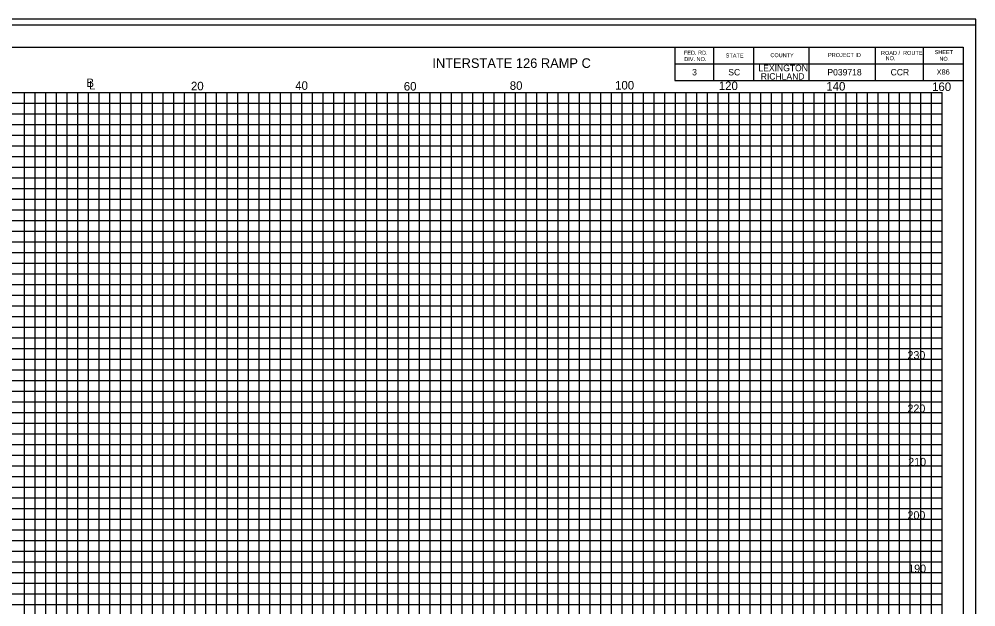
# Model space of a CAD drawing. Extents: x 967 to 1326, y 964 to 2584.
# Drawn here: x 1147 to 1326.3, y 1353.6 to 1463.7 of the extents above; entities that cross this region are included whole.
import ezdxf

# ---------------------------------------------------------------- set-up
doc = ezdxf.new("R2010")
doc.units = 0
for name, color, linetype in [('Default', 7, 'Continuous'), ('RD_SHT_Bndy', 7, 'Continuous'), ('RD_SHT_IplotShp', 7, 'Continuous'), ('RD_SHT_MjGrid', 7, 'Continuous'), ('RD_SHT_MnGrid', 7, 'Continuous'), ('RD_SHT_TX', 7, 'Continuous'), ('RD_Sketch1', 7, 'Continuous')]:
    doc.layers.add(name, color=color, linetype=linetype)

msp = doc.modelspace()

# ---------------------------------------------------------------- linework, layer by layer
at = {"layer": 'RD_SHT_Bndy'}
for p, q in [((996.11, 1458.46), (1323.89, 1458.46)), ((1269.89, 1458.46), (1269.89, 1452.21)), ((1277.14, 1458.46), (1277.14, 1452.21)), ((1284.64, 1458.46), (1284.64, 1452.21)), ((1295, 1458.46), (1295, 1452.21)), ((1307.43, 1458.46), (1307.43, 1452.21)), ((1316.39, 1458.46), (1316.39, 1452.21)), ((1323.89, 1458.46), (1323.89, 1248.98)), ((1269.89, 1455.33), (1323.89, 1455.33)), ((1269.89, 1452.21), (1323.89, 1452.21))]:
    msp.add_line(p, q, dxfattribs=at)
at = {"layer": 'RD_SHT_IplotShp'}
for points in [[(967.41, 1243.72), (1326.28, 1243.72), (1326.28, 1463.72), (967.41, 1463.72)], [(988.52, 1244.84), (1326.28, 1244.84), (1326.28, 1462.6), (988.52, 1462.6)]]:
    msp.add_lwpolyline(points, close=True, dxfattribs=at)
at = {"layer": 'RD_SHT_MjGrid'}
for p, q in [((1000, 1450), (1320, 1450)), ((1150, 1280), (1150, 1450)), ((1160, 1280), (1160, 1450)), ((1170, 1280), (1170, 1450)), ((1180, 1280), (1180, 1450)), ((1190, 1280), (1190, 1450)), ((1200, 1280), (1200, 1450)), ((1210, 1280), (1210, 1450)), ((1220, 1280), (1220, 1450)), ((1230, 1280), (1230, 1450)), ((1240, 1280), (1240, 1450)), ((1250, 1280), (1250, 1450)), ((1260, 1280), (1260, 1450)), ((1270, 1280), (1270, 1450)), ((1280, 1280), (1280, 1450)), ((1290, 1280), (1290, 1450)), ((1300, 1280), (1300, 1450)), ((1310, 1280), (1310, 1450)), ((1320, 1280), (1320, 1450)), ((1000, 1440), (1320, 1440)), ((1000, 1430), (1320, 1430)), ((1000, 1420), (1320, 1420)), ((1000, 1410), (1320, 1410)), ((1000, 1400), (1320, 1400)), ((1000, 1390), (1320, 1390)), ((1000, 1380), (1320, 1380)), ((1000, 1370), (1320, 1370)), ((1000, 1360), (1320, 1360))]:
    msp.add_line(p, q, dxfattribs=at)
at = {"layer": 'RD_SHT_MnGrid'}
for p, q in [((1148, 1280), (1148, 1450)), ((1152, 1280), (1152, 1450)), ((1154, 1280), (1154, 1450)), ((1156, 1280), (1156, 1450)), ((1158, 1280), (1158, 1450)), ((1162, 1280), (1162, 1450)), ((1164, 1280), (1164, 1450)), ((1166, 1280), (1166, 1450)), ((1168, 1280), (1168, 1450)), ((1172, 1280), (1172, 1450)), ((1174, 1280), (1174, 1450)), ((1176, 1280), (1176, 1450)), ((1178, 1280), (1178, 1450)), ((1182, 1280), (1182, 1450)), ((1184, 1280), (1184, 1450)), ((1186, 1280), (1186, 1450)), ((1188, 1280), (1188, 1450)), ((1192, 1280), (1192, 1450)), ((1194, 1280), (1194, 1450)), ((1196, 1280), (1196, 1450)), ((1198, 1280), (1198, 1450)), ((1202, 1280), (1202, 1450)), ((1204, 1280), (1204, 1450)), ((1206, 1280), (1206, 1450)), ((1208, 1280), (1208, 1450)), ((1212, 1280), (1212, 1450)), ((1214, 1280), (1214, 1450)), ((1216, 1280), (1216, 1450)), ((1218, 1280), (1218, 1450)), ((1222, 1280), (1222, 1450)), ((1224, 1280), (1224, 1450)), ((1226, 1280), (1226, 1450)), ((1228, 1280), (1228, 1450)), ((1232, 1280), (1232, 1450)), ((1234, 1280), (1234, 1450)), ((1236, 1280), (1236, 1450)), ((1238, 1280), (1238, 1450)), ((1242, 1280), (1242, 1450)), ((1244, 1280), (1244, 1450)), ((1246, 1280), (1246, 1450)), ((1248, 1280), (1248, 1450)), ((1252, 1280), (1252, 1450)), ((1254, 1280), (1254, 1450)), ((1256, 1280), (1256, 1450)), ((1258, 1280), (1258, 1450)), ((1262, 1280), (1262, 1450)), ((1264, 1280), (1264, 1450)), ((1266, 1280), (1266, 1450)), ((1268, 1280), (1268, 1450)), ((1272, 1280), (1272, 1450)), ((1274, 1280), (1274, 1450)), ((1276, 1280), (1276, 1450)), ((1278, 1280), (1278, 1450)), ((1282, 1280), (1282, 1450)), ((1284, 1280), (1284, 1450)), ((1286, 1280), (1286, 1450)), ((1288, 1280), (1288, 1450)), ((1292, 1280), (1292, 1450)), ((1294, 1280), (1294, 1450)), ((1296, 1280), (1296, 1450)), ((1298, 1280), (1298, 1450)), ((1302, 1280), (1302, 1450)), ((1304, 1280), (1304, 1450)), ((1306, 1280), (1306, 1450)), ((1308, 1280), (1308, 1450)), ((1312, 1280), (1312, 1450)), ((1314, 1280), (1314, 1450)), ((1316, 1280), (1316, 1450)), ((1318, 1280), (1318, 1450)), ((1000, 1448), (1320, 1448)), ((1000, 1446), (1320, 1446)), ((1000, 1444), (1320, 1444)), ((1000, 1442), (1320, 1442)), ((1000, 1438), (1320, 1438)), ((1000, 1436), (1320, 1436)), ((1000, 1434), (1320, 1434)), ((1000, 1432), (1320, 1432)), ((1000, 1428), (1320, 1428)), ((1000, 1426), (1320, 1426)), ((1000, 1424), (1320, 1424)), ((1000, 1422), (1320, 1422)), ((1000, 1418), (1320, 1418)), ((1000, 1416), (1320, 1416)), ((1000, 1414), (1320, 1414)), ((1000, 1412), (1320, 1412)), ((1000, 1408), (1320, 1408)), ((1000, 1406), (1320, 1406)), ((1000, 1404), (1320, 1404)), ((1000, 1402), (1320, 1402)), ((1000, 1398), (1320, 1398)), ((1000, 1396), (1320, 1396)), ((1000, 1394), (1320, 1394)), ((1000, 1392), (1320, 1392)), ((1000, 1388), (1320, 1388)), ((1000, 1386), (1320, 1386)), ((1000, 1384), (1320, 1384)), ((1000, 1382), (1320, 1382)), ((1000, 1378), (1320, 1378)), ((1000, 1376), (1320, 1376)), ((1000, 1374), (1320, 1374)), ((1000, 1372), (1320, 1372)), ((1000, 1368), (1320, 1368)), ((1000, 1366), (1320, 1366)), ((1000, 1364), (1320, 1364)), ((1000, 1362), (1320, 1362)), ((1000, 1358), (1320, 1358)), ((1000, 1356), (1320, 1356)), ((1000, 1354), (1320, 1354))]:
    msp.add_line(p, q, dxfattribs=at)
at = {"layer": 'RD_Sketch1'}
msp.add_lwpolyline([(967.41, 1243.72), (1326.28, 1243.72), (1326.28, 1463.72), (967.41, 1463.72)], close=True, dxfattribs=at)

# ---------------------------------------------------------------- texts
at = {"layer": 'Default'}
for s, height, p in [('X86', 1, (1318.94, 1453.3)), ('230', 1.5, (1313.47, 1400)), ('220', 1.5, (1313.47, 1390)), ('210', 1.5, (1313.61, 1380)), ('200', 1.5, (1313.47, 1370)), ('190', 1.5, (1313.61, 1360))]:
    msp.add_text(s, height=height, dxfattribs=at).set_placement(p)
at = {"layer": 'RD_SHT_TX'}
for s, height, p in [('FED. RD.', 0.75, (1271.58, 1457.05)), ('ROAD /  ROUTE', 0.75, (1308.51, 1457.01)), ('SHEET', 0.75, (1318.56, 1457.16)), ('DIV. NO.', 0.75, (1271.64, 1455.86)), ('STATE', 0.75, (1279.41, 1456.53)), ('COUNTY', 0.75, (1287.78, 1456.59)), ('PROJECT ID', 0.75, (1298.58, 1456.63)), ('   NO.', 0.75, (1308.51, 1456.03)), ('NO.', 0.75, (1319.45, 1455.91)), ('3', 1.2, (1273.12, 1453.17)), ('SC', 1.2, (1279.89, 1453.17)), ('LEXINGTON', 1.2, (1285.54, 1453.96)), ('P039718', 1.2, (1298.46, 1453.17)), ('CCR', 1.2, (1310.31, 1453.17)), ('B', 1.6, (1159.61, 1450.99)), ('RICHLAND', 1.2, (1285.97, 1452.39)), ('L', 1.6, (1160.12, 1450.54)), ('20', 1.6, (1179.2, 1450.38)), ('40', 1.6, (1198.74, 1450.47)), ('60', 1.6, (1219.08, 1450.33)), ('80', 1.6, (1238.94, 1450.47)), ('100', 1.6, (1258.67, 1450.53)), ('120', 1.6, (1278.11, 1450.43)), ('140', 1.6, (1298.26, 1450.34)), ('160', 1.6, (1318.08, 1450.25))]:
    msp.add_text(s, height=height, dxfattribs=at).set_placement(p)
msp.add_text('INTERSTATE 126 RAMP C', height=1.8, rotation=0, dxfattribs=at).set_placement((1224.44, 1454.58))

doc.saveas('drawing.dxf')
